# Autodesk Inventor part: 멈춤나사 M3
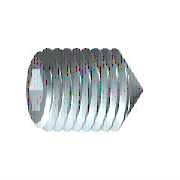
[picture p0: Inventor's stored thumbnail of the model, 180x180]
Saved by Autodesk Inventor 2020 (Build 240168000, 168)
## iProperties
Created: 2012-02
Part Number: 멈춤나사 M3
Material: 강철, 연강
Description: 6각 소켓 머리 없는 멈춤 나사
Document SubType Name: Modeling
Standard: KS B 1028
Designer: test
Standards Organization: KS
Language: ko-KR
Size Designation: 원추점 M3x8
Categories: <MemberInstance><Categories><Category DisplayName="조임쇠" InternalName="e4da775c-781d-43d5-af7c-5136215cf5a6" Mnemonic="FSTN"><Category DisplayName="볼트" InternalN
Density: 1 g/cm^3
Appearance: 강철
IsCustomPart: 1
Author: test
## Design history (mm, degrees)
sketch "스케치1"
  geometry: L1 (0, 0)-(3.5, 0); L2 (6, 0.866)-(6, 1.5); L3 (6, 1.5)-(0, 1.5); L4 (6, 0.866)-(4, 0.866); L5 (4, 0.866)-(3.5, 0); L6 (0, -0.3)-(0, 1.8) reference; L7 (0, 1.5)-(0, 0)
  constraints: 13 end point, 3 parallel, 1 collinear, 1 perpendicular, 1 point on line
  dimensions: "d0" = 2 distance of L2.start L4.end (= INTI); "d1" = 60 deg angle of L5 L1; "d2" = 3 diameter of L3 L1 (= NND); "d3" = 1.73205 diameter of L4 L1 (= 1.1547 x SW); "d5" = 6 distance from line of L2 L3.end (= NLG)
revolve "본체" sketch "스케치1" stored, may be unused: angle "d6" = 90 deg
sketch "스케치2"
  geometry: L1 (-0.433, 0.75)-(0.433, 0.75); L2 (0.433, 0.75)-(0.866, 0); L3 (0.866, 0)-(0.433, -0.75); L4 (0.433, -0.75)-(-0.433, -0.75); L5 (-0.433, -0.75)-(-0.866, 0); L6 (-0.866, 0)-(-0.433, 0.75); 3 further points
  constraints: 12 end point, 1 coincident, 1 horizontal, 13 other
extrude "슬롯" join sketch "스케치2" taper "d7" = 0 deg; stored distance "d21" = 10
workaxis "Work Axis1"
workplane "Work Plane1"
sketch "스케치4"
  geometry: L1 (0, 0.15)-(-1.35, 1.5) reference; L2 (0, -0.15)-(-1.35, -1.5) reference; L3 (-1.35, -1.5)-(0.15, 0); L4 (-1.35, 1.5)-(0.15, 0); 2 further points
  constraints: 4 end point, 1 coincident, 1 collinear, 1 horizontal alignment
node "작업점1"
body "Solid1"
feature "스레드" dims "d12" = 6 (= NLG), "d13" = 0
chamfer "모따기1" distance "d8" = 1.35 (computed from NND, SPD, FAWI); stored, may be unused: angle "d9" = 45 deg (= FAWI), second distance "d34" = 1.35 (computed from NND, SPD, FAWI)
chamfer "모따기2" distance "d10" = 0.30673 (= -0.5 x GD1 + 0.5 x NND); stored, may be unused: angle "d11" = 45 deg (= FAWI), second distance "d35" = 0.30673 (= -0.5 x GD1 + 0.5 x NND)
other parameters: "NND" = 3 [user parameter; used in 5 equation terms], "NLG" = 6 [user parameter; used in 2 equation terms], "INTI" = 2 [user parameter; used in 1 equation term], "FAWI" = 45 deg [user parameter; used in 4 equation terms], "SW" = 1.5 [user parameter; used in 2 equation terms], "GD1" = 2.38655 (= THREADDIA - 1.2269 x PTC) [user parameter; used in 2 equation terms], "d4" = 0, "FAWI1" = 45 deg [user parameter], "SPD" = 0.3 [user parameter; used in 2 equation terms], "d36" = 0, "d37" = 0, "GUL" = 0.30673 (= 0.61345 x PTC) [user parameter], "TOA" = 30 deg [user parameter], "THREADDIA" = 3 [user parameter; used in 1 equation term], "PTC" = 0.5 [user parameter; used in 4 equation terms], "GAL" = 0.30673 (= 0.61345 x PTC) [user parameter], "E0" = 1.7325 (= 1.155 x SW) [user parameter]
